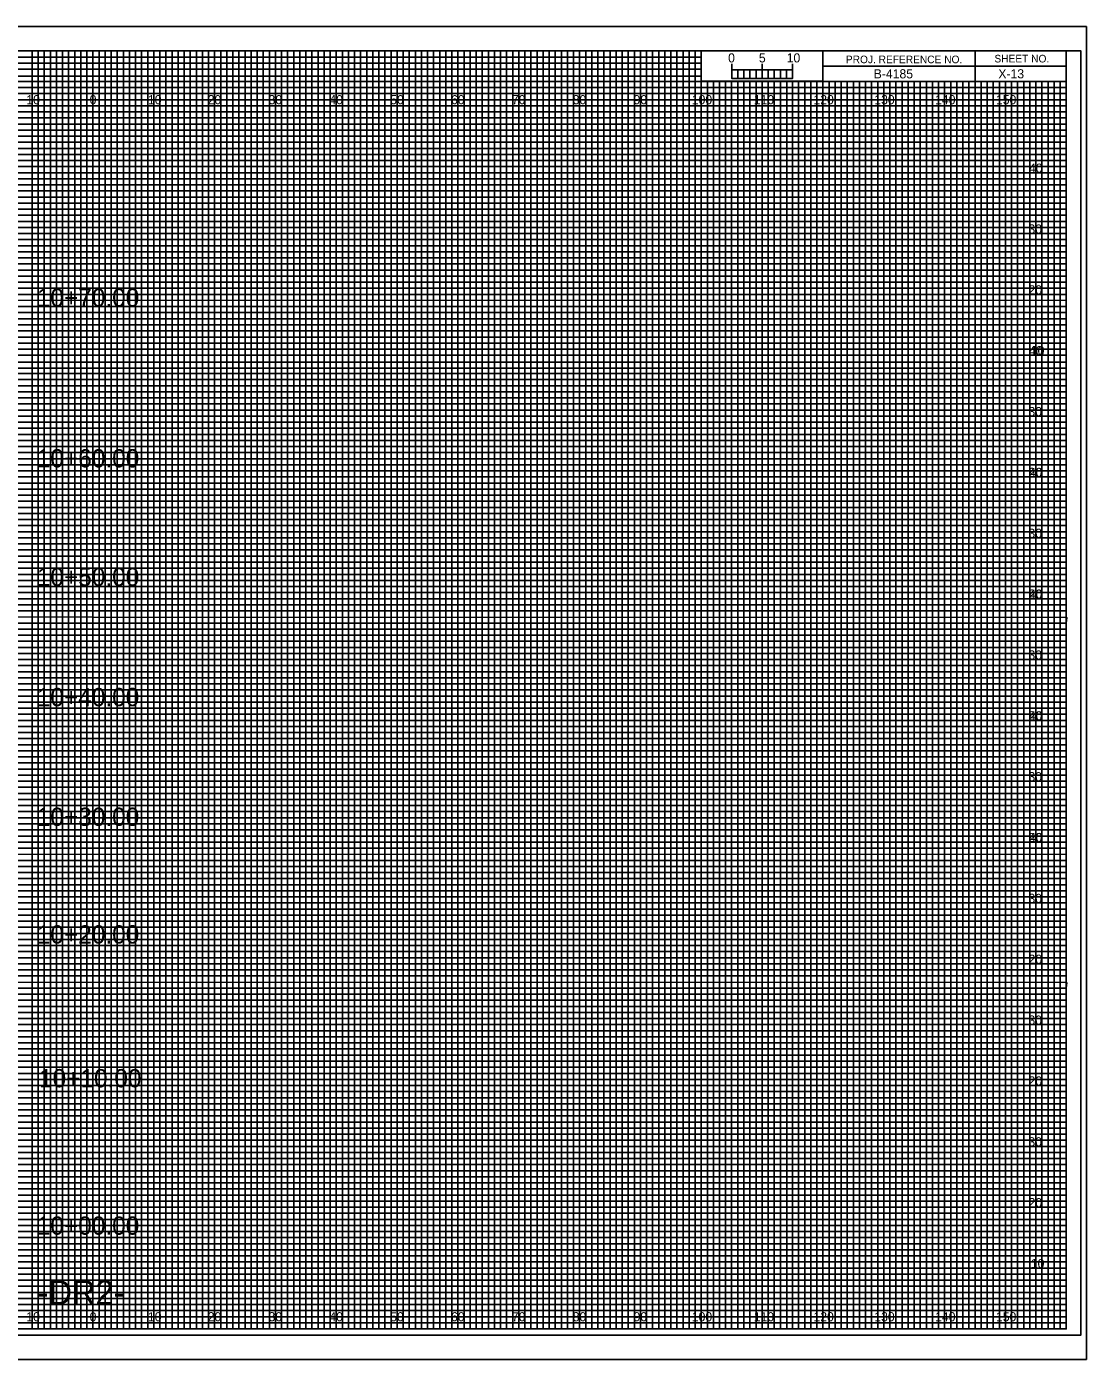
# Model space of a CAD drawing. Extents: x -13 to 323, y -5 to 214.
# Drawn here: x 149.1 to 323.3, y -5 to 214 of the extents above; entities that cross this region are included whole.
import ezdxf

# ---------------------------------------------------------------- set-up
doc = ezdxf.new("R2010")
doc.units = 0
for name, color, linetype in [('Prop XS Alignment Label', 7, 'Continuous'), ('Prop XS Bar Scale Labels', 7, 'Continuous'), ('Prop XS Elevation Labels', 7, 'Continuous'), ('Prop XS Offset Labels', 7, 'Continuous'), ('Prop XS Project Number', 7, 'Continuous'), ('Prop XS Sheet Number', 7, 'Continuous'), ('Prop XS Station Labels', 7, 'Continuous'), ('Sheet Cross Section CELL', 7, 'Continuous'), ('Sheet Cross Section Grid Major CELL', 7, 'Continuous'), ('Sheet Cross Section Grid Middle CELL', 7, 'Continuous'), ('Sheet Cross Section Grid Minor 1 CELL', 7, 'Continuous'), ('Sheet Cross Section Grid Minor 2 CELL', 7, 'Continuous'), ('Sheet Cross Section Scale CELL', 7, 'Continuous'), ('Sheet Cutting Line CELL', 7, 'Continuous'), ('Sheet DOT Grid CELL', 7, 'Continuous'), ('Sheet Plot Border Inside CELL', 7, 'Continuous'), ('Sheet Plot Border Outside CELL', 7, 'Continuous')]:
    doc.layers.add(name, color=color, linetype=linetype)

msp = doc.modelspace()

# ---------------------------------------------------------------- linework, layer by layer
at = {"layer": 'Sheet Cross Section CELL'}
for p, q in [((305, 210), (305, 205)), ((305, 205), (305, 210)), ((280, 207.5), (280, 205)), ((320, 207.49), (280, 207.49)), ((280, 205), (320, 205))]:
    msp.add_line(p, q, dxfattribs=at)
for points in [[(320, 210), (0, 210), (0, 0), (320, 0)], [(280, 210), (260, 210), (260, 205.03), (280, 205.03)], [(320, 210), (280, 210), (280, 205), (320, 205)]]:
    msp.add_lwpolyline(points, close=True, dxfattribs=at)
at = {"layer": 'Sheet Cross Section Grid Major CELL'}
for p, q in [((150, 210), (140, 210)), ((150, 0), (150, 210)), ((170, 210), (160, 210)), ((160, 210), (160, 0)), ((170, 0), (170, 210)), ((190, 210), (180, 210)), ((180, 210), (180, 0)), ((190, 0), (190, 210)), ((210, 210), (200, 210)), ((200, 210), (200, 0)), ((210, 0), (210, 210)), ((230, 210), (220, 210)), ((220, 210), (220, 0)), ((230, 0), (230, 210)), ((250, 210), (240, 210)), ((240, 210), (240, 0)), ((250, 0), (250, 210)), ((260, 210), (260, 0)), ((270, 0), (270, 205)), ((290, 205), (280, 205)), ((280, 205), (280, 0)), ((290, 0), (290, 205)), ((310, 205), (300, 205)), ((300, 205), (300, 0)), ((310, 0), (310, 205)), ((160, 0), (150, 0)), ((180, 0), (170, 0)), ((200, 0), (190, 0)), ((220, 0), (210, 0)), ((240, 0), (230, 0)), ((260, 0), (250, 0)), ((280, 0), (270, 0)), ((300, 0), (290, 0)), ((320, 0), (310, 0)), ((320, 0), (320, 0))]:
    msp.add_line(p, q, dxfattribs=at)
for points in [[(0, 200), (320, 200), (320, 190), (0, 190)], [(0, 180), (320, 180), (320, 170), (0, 170)], [(0, 160), (320, 160), (320, 150), (0, 150)], [(0, 140), (320, 140), (320, 130), (0, 130)], [(0, 120), (320, 120), (320, 110), (0, 110)], [(0, 100), (320, 100), (320, 90), (0, 90)], [(0, 80), (320, 80), (320, 70), (0, 70)], [(0, 60), (320, 60), (320, 50), (0, 50)], [(0, 40), (320, 40), (320, 30), (0, 30)], [(0, 20), (320, 20), (320, 10), (0, 10)]]:
    msp.add_lwpolyline(points, dxfattribs=at)
at = {"layer": 'Sheet Cross Section Grid Middle CELL'}
for points in [[(145, 0), (155, 0), (155, 210), (165, 210), (165, 0), (175, 0), (175, 210), (185, 210), (185, 0), (195, 0), (195, 210), (205, 210), (205, 0), (215, 0), (215, 210), (225, 210), (225, 0), (235, 0), (235, 210), (245, 210), (245, 0), (255, 0), (255, 210), (259.93, 210), (260, 210), (260, 205), (264.99, 205), (264.99, 0), (275, 0), (275, 205), (285, 205), (285, 0), (295, 0), (295, 205), (305, 205), (305, 0), (315, 0), (315, 205)], [(0, 205), (275, 205)], [(0, 185), (320, 185), (320, 195), (0, 195)], [(0, 165), (320, 165), (320, 175), (0, 175)], [(0, 145), (320, 145), (320, 155), (0, 155)], [(0, 125), (320, 125), (320, 135), (0, 135)], [(0, 105), (320, 105), (320, 115), (0, 115)], [(0, 85), (320, 85), (320, 95), (0, 95)], [(0, 65), (320, 65), (320, 75), (0, 75)], [(0, 45), (320, 45), (320, 55), (0, 55)], [(0, 25), (320, 25), (320, 35), (0, 35)], [(0, 5), (320, 5), (320, 15), (0, 15)]]:
    msp.add_lwpolyline(points, dxfattribs=at)
at = {"layer": 'Sheet Cross Section Grid Minor 1 CELL'}
for p, q in [((0, 209), (260, 209)), ((260, 209), (260, 207.98)), ((260, 207.98), (0, 207.98)), ((0, 207), (260, 207)), ((260, 205.89), (0, 205.89)), ((260, 207), (260, 205.89)), ((0, 204), (320, 204))]:
    msp.add_line(p, q, dxfattribs=at)
for points in [[(0, 203), (270, 203), (320, 203), (320, 202), (0, 202)], [(0, 201), (320, 201), (320, 199), (0, 199)], [(0, 198), (320, 198), (320, 197), (0, 196.98)], [(0, 196), (320, 196), (320, 194), (0, 194)], [(0, 193), (320, 193), (320, 192), (0, 192)], [(0, 191), (320, 191), (320, 189), (0, 189)], [(0, 188), (320, 188), (320, 187), (0, 187)], [(0, 186), (320, 186), (320, 184), (0, 184)], [(0, 183), (320, 183), (320, 182), (0, 182)], [(0, 181), (320, 181), (320, 179), (0, 179)], [(0, 178), (320, 178), (320, 177), (0, 177)], [(0, 176), (320, 176), (320, 173.95), (320, 173), (320, 172), (0, 172)], [(0, 174), (320, 174), (320, 173), (0, 173)], [(0, 171), (320, 171), (320, 169), (0, 169.03)], [(0, 169.03), (320, 169), (320, 168), (0, 168)], [(0, 167), (320, 167), (320, 166), (0, 166)], [(0, 164), (320, 164), (320, 163), (0, 163)], [(0, 162), (320, 162), (320, 161), (0, 161)], [(-0.07, 158.89), (320, 158.89), (320, 157.88), (-0.07, 157.88)], [(0, 157), (320, 157), (320, 156), (0, 156)], [(0, 154), (320, 154), (320, 153), (0, 153)], [(0, 152), (320, 152), (320, 151), (0, 151)], [(0, 149), (320, 149), (320, 148), (0, 148)], [(0, 147), (320, 147), (320, 146), (0, 146)], [(0, 144), (320, 144), (320, 143), (0, 143)], [(0, 142), (320, 142), (320, 141), (0, 141)], [(0, 139), (320, 139), (319.99, 137.98), (0, 138)], [(0, 137), (320, 137), (320, 136), (0, 136)], [(0, 134), (320, 134), (320, 133), (0, 133)], [(0, 132), (320, 132), (320, 131), (0, 131)], [(0, 129), (320, 129), (320, 128), (0, 128)], [(0, 127), (320, 127), (320, 126), (0, 126)], [(0, 124), (320, 124), (320, 123), (0, 123)], [(0, 122), (320, 122), (320, 121), (0, 121)], [(0, 119), (320, 119), (320, 118), (0, 118)], [(0, 116.99), (320.07, 116.91), (320, 116), (0, 116)], [(0, 114), (320, 114), (320, 113), (0, 113)], [(0, 112), (320, 112), (320, 111), (0, 111)], [(0, 109), (320, 109), (320, 108), (0, 108)], [(0, 107), (320, 107), (320, 106), (0, 106)], [(0, 104), (320, 104), (320, 103), (0, 103)], [(0, 102), (320, 102), (320, 101), (0, 101)], [(0, 99), (320, 99), (320, 98), (0, 98)], [(0, 97), (320, 97), (320, 96), (0, 96)], [(0, 94), (320, 94), (320, 93), (0, 93)], [(0, 92), (320, 92), (320, 91), (0, 91)], [(0, 89), (320, 89), (320, 88), (0, 88)], [(0, 87), (320, 87), (320, 86), (0, 86)], [(0, 84), (320, 84), (320, 83), (0, 83)], [(0, 82), (320, 82), (320, 81), (0, 81)], [(0, 79), (320, 79), (319.99, 77.98), (0, 78)], [(0, 77), (320, 77), (320, 76), (0, 76)], [(0, 74), (320, 74), (320, 73), (0, 73)], [(0, 72), (320, 72), (320, 71), (0, 71)], [(0, 69), (320, 69), (320, 68), (0, 68)], [(0, 67), (320, 67), (320, 66), (0, 66)], [(0, 64), (320, 64), (320, 63), (0, 63)], [(0, 62), (320, 62), (320, 61), (0, 61)], [(0, 59), (320, 59), (320, 58), (0, 58)], [(0, 56.99), (320.07, 56.91), (320, 56), (0, 56)], [(0, 54), (320, 54), (320, 53), (0, 53)], [(0, 52), (320, 52), (320, 51), (0, 51)], [(0, 49), (320, 49), (320, 48), (0, 48)], [(0, 47), (320, 47), (320, 46), (0, 46)], [(0, 44), (320, 44), (320, 43), (0, 43)], [(0, 42), (320, 42), (320, 41), (0, 41)], [(0, 39), (320, 39), (320, 38), (0, 38)], [(0, 37), (320, 37), (320, 36), (0, 36)], [(0, 34), (320, 34), (320, 33), (0, 33)], [(0, 32), (320, 32), (320, 31), (0, 31)], [(0, 29), (320, 29), (320, 28), (0, 28)], [(0, 27), (320, 27), (320, 26), (0, 26)], [(0, 24), (320, 24), (320, 23), (0, 23)], [(0, 22), (320, 22), (320, 21), (0, 21)], [(0, 19), (320, 19), (320, 18), (0, 18)], [(0, 17), (320, 17), (320, 16), (0, 16)], [(0, 14), (320, 14), (320, 13), (0, 13)], [(0, 12), (320, 12), (320, 11), (0, 11)], [(0, 9), (320, 9), (320, 8), (0, 8)], [(0, 7), (320, 7), (320, 6), (0, 6)], [(0, 4), (320, 4), (320, 3), (0, 3)], [(0, 2), (320, 2), (320, 1), (0, 1)]]:
    msp.add_lwpolyline(points, dxfattribs=at)
at = {"layer": 'Sheet Cross Section Grid Minor 2 CELL'}
for p, q in [((267, 205), (266.01, 205)), ((266.01, 205), (266.01, 0)), ((267, 0), (267, 205)), ((269, 205), (268, 205)), ((268, 205), (268, 0)), ((269, 0), (269, 205)), ((266.01, 0), (265, 0)), ((268, 0), (267, 0))]:
    msp.add_line(p, q, dxfattribs=at)
for points in [[(150, 0), (151, 0), (151, 210), (152, 210), (152, 0)], [(152, 0), (153, 0), (153, 210), (154, 210), (154, 0)], [(155, 0), (156, 0), (156, 210), (157, 210), (157, 0)], [(157, 0), (158, 0), (158, 210), (159, 210), (159, 0)], [(160, 0), (161, 0), (161, 210), (162, 210), (162, 0)], [(162, 0), (163, 0), (163, 210), (164, 210), (164, 0)], [(165, 0), (166, 0), (166, 210), (167, 210), (167, 0)], [(167, 0), (168, 0), (168, 210), (169, 210), (169, 0)], [(170, 0), (171, 0), (171, 210), (172, 210), (172, 0)], [(172, 0), (173, 0), (173, 210), (174, 210), (174, 0)], [(175, 0), (176, 0), (176, 210), (177, 210), (177, 0)], [(177, 0), (178, 0), (178, 210), (179, 210), (179, 0)], [(180, 0), (181, 0), (181, 210), (182, 210), (182, 0)], [(182, 0), (183, 0), (183, 210), (184, 210), (184, 0)], [(185, 0), (186, 0), (186, 210), (187, 210), (187, 0)], [(187, 0), (188, 0), (188, 210), (189, 210), (189, 0)], [(190, 0), (191, 0), (191, 210), (192, 210), (192, 0)], [(192, 0), (193, 0), (193, 210), (194, 210), (194, 0)], [(195, 0), (196, 0), (196, 210), (197, 210), (197, 0)], [(197, 0), (198, 0), (198, 210), (199, 210), (199, 0)], [(200, 0), (201, 0), (201, 210), (202, 210), (202, 0)], [(202, 0), (203, 0), (203, 210), (204, 210), (204, 0)], [(205, 0), (206, 0), (206, 210), (207, 210), (207, 0)], [(207, 0), (208, 0), (208, 210), (209, 210), (209, 0)], [(210, 0), (211, 0), (211, 210), (212, 210), (212, 0)], [(212, 0), (213, 0), (213, 210), (214, 210), (214, 0)], [(215, 0), (216, 0), (216, 210), (217, 210), (217, 0)], [(217, 0), (218, 0), (218, 210), (219, 210), (219, 0)], [(220, 0), (221, 0), (221, 210), (222, 210), (222, 0)], [(222, 0), (223, 0), (223, 210), (224, 210), (224, 0)], [(225, 0), (226, 0), (226, 210), (227, 210), (227, 0)], [(227, 0), (228, 0), (228, 210), (229, 210), (229, 0)], [(230, 0), (231, 0), (231, 210), (232, 210), (232, 0)], [(232, 0), (233, 0), (233, 210), (234, 210), (234, 0)], [(235, 0), (236, 0), (236, 210), (237, 210), (237, 0)], [(237, 0), (238, 0), (238, 210), (239, 210), (239, 0)], [(240, 0), (241, 0), (241, 210), (242, 210), (242, 0)], [(242, 0), (243, 0), (243, 210), (244, 210), (244, 0)], [(245, 0), (246, 0), (246, 210), (247, 210), (247, 0)], [(247, 0), (248, 0), (248, 210), (249, 210), (249, 0)], [(250, 0), (251, 0), (251, 210), (252, 210), (252, 0)], [(252, 0), (253, 0), (253, 210), (254, 210), (254, 0)], [(255, 0), (256, 0), (256, 210), (257, 210), (257, 0)], [(257, 0), (258, 0), (258, 210), (259, 210), (259, 0)], [(260, 0), (261, 0), (261, 205), (262.02, 205), (262.02, 0)], [(262, 0), (263, 0), (263, 205), (263.99, 205), (263.99, 0)], [(270, 0), (270.98, 0), (270.98, 205), (272, 205), (272, 0)], [(272, 0), (273, 0), (273, 205), (274.05, 205), (274.05, 0)], [(275, 0), (276, 0), (276, 205), (277, 205), (277, 0)], [(277, 0), (278, 0), (278, 205), (279, 205), (279, 0)], [(280, 0), (281, 0), (281, 205), (282, 205), (282, 0)], [(282, 0), (283, 0), (283, 205), (284, 205), (284, 0)], [(285, 0), (286, 0), (286, 205), (287, 205), (287, 0)], [(287, 0), (288, 0), (288, 205), (289, 205), (289, 0)], [(290, 0), (291, 0), (291, 205), (292, 205), (292, 0)], [(292, 0), (293, 0), (293, 205), (294, 205), (294, 0)], [(295, 0), (296, 0), (296, 205), (297, 205), (297, 0)], [(297, 0), (298, 0), (298, 205), (299, 205), (299, 0)], [(300, 0), (301, 0), (301, 205), (302, 205), (302, 0)], [(302, 0), (303, 0), (303, 205), (304, 205), (304, 0)], [(305, 0), (306, 0), (306, 205), (307, 205), (307, 0)], [(307, 0), (308, 0), (308, 205), (309, 205), (309, 0)], [(310, 0), (311, 0), (311, 205), (312, 205), (312, 0)], [(312, 0), (313, 0), (313, 205), (314, 205), (314, 0)], [(315, 0), (316, 0), (316, 205), (317, 205), (317, 0)], [(317, 0), (318, 0), (318, 205), (319, 205), (319, 0)]]:
    msp.add_lwpolyline(points, dxfattribs=at)
at = {"layer": 'Sheet Cross Section Scale CELL'}
for p, q in [((265, 205.49), (265, 207.9)), ((265, 206.9), (265, 207.9)), ((270, 205.49), (270, 207.9)), ((275, 205.49), (275, 207.9)), ((275, 206.9), (275, 207.9))]:
    msp.add_line(p, q, dxfattribs=at)
for points in [[(275, 206.9), (265, 206.9), (265, 205.49), (275, 205.49)], [(265, 206.9), (266, 206.9), (266, 205.49), (265, 205.49)], [(267, 206.9), (268, 206.9), (268, 205.49), (267, 205.49)], [(269, 206.9), (270, 206.9), (270, 205.49), (269, 205.49)], [(271, 206.9), (272, 206.9), (272, 205.49), (271, 205.49)], [(273, 206.9), (274, 206.9), (274, 205.49), (273, 205.49)]]:
    msp.add_lwpolyline(points, close=True, dxfattribs=at)
at = {"layer": 'Sheet Cutting Line CELL'}
for p, q in [((323.3, 214), (-13.4, 214)), ((-13.4, -5), (323.3, -5))]:
    msp.add_line(p, q, dxfattribs=at)
at = {"layer": 'Sheet DOT Grid CELL'}
for p, q in [((150, 0), (150, 210)), ((160, 0), (160, 210)), ((170, 0), (170, 210)), ((180, 0), (180, 210)), ((190, 0), (190, 210)), ((200, 0), (200, 210)), ((210, 0), (210, 210)), ((220, 0), (220, 210)), ((230, 0), (230, 210)), ((240, 0), (240, 210)), ((250, 0), (250, 210)), ((260, 0), (260, 204.69)), ((270, 0), (270, 204.69)), ((280, 0), (280, 204.69)), ((290, 0), (290, 204.69)), ((300, 0), (300, 204.69)), ((310, 0), (310, 204.69)), ((0, 200), (320, 200)), ((0, 190), (320, 190)), ((0, 180), (320, 180)), ((0, 170), (320, 170)), ((0, 160), (320, 160)), ((0, 150), (320, 150)), ((0, 140), (320, 140)), ((0, 130), (320, 130)), ((0, 120), (320, 120)), ((0, 110), (320, 110)), ((0, 100), (320, 100)), ((0, 90), (320, 90)), ((0, 80), (320, 80)), ((0, 70), (320, 70)), ((0, 60), (320, 60)), ((0, 50), (320, 50)), ((0, 40), (320, 40)), ((0, 30), (320, 30)), ((0, 20), (320, 20)), ((0, 10), (320, 10))]:
    msp.add_line(p, q, dxfattribs=at)
at = {"layer": 'Sheet Plot Border Inside CELL'}
msp.add_lwpolyline([(-10.8, -1), (322.4, -1), (322.4, 210), (-10.8, 210)], close=True, dxfattribs=at)
at = {"layer": 'Sheet Plot Border Outside CELL'}
msp.add_lwpolyline([(-13.4, -5), (323.3, -5), (323.3, 214), (-13.4, 214)], close=True, dxfattribs=at)

# ---------------------------------------------------------------- texts
at = {"layer": 'Prop XS Alignment Label'}
msp.add_text('-DR2-', height=4, dxfattribs=at).set_placement((150.91, 4))
at = {"layer": 'Prop XS Bar Scale Labels'}
for s, p in [('5', (269.47, 208.12)), ('10', (274.04, 208.12))]:
    msp.add_text(s, height=1.5, dxfattribs=at).set_placement(p)
at = {"layer": 'Prop XS Elevation Labels'}
for s, p in [('40', (313.87, 190)), ('30', (313.78, 180)), ('20', (313.8, 170)), ('40', (313.87, 160)), ('10', (314.17, 160)), ('30', (313.78, 150)), ('20', (313.8, 140)), ('40', (313.87, 140)), ('30', (313.78, 130)), ('20', (313.8, 120)), ('40', (313.87, 120)), ('30', (313.78, 110)), ('20', (313.8, 100)), ('40', (313.87, 100)), ('30', (313.78, 90)), ('20', (313.8, 80)), ('40', (313.87, 80)), ('30', (313.78, 70)), ('20', (313.8, 60)), ('30', (313.78, 50)), ('20', (313.8, 40)), ('30', (313.78, 30)), ('20', (313.8, 20)), ('10', (314.17, 10))]:
    msp.add_text(s, height=1.5, dxfattribs=at).set_placement(p)
at = {"layer": 'Prop XS Offset Labels'}
for s, p in [('10', (149.04, 201.25)), ('0', (159.45, 201.25)), ('0', (159.45, 201.25)), ('10', (169.04, 201.25)), ('20', (178.86, 201.25)), ('30', (188.86, 201.25)), ('40', (198.86, 201.25)), ('50', (208.86, 201.25)), ('60', (218.86, 201.25)), ('70', (228.86, 201.25)), ('80', (238.86, 201.25)), ('90', (248.86, 201.25)), ('100', (258.44, 201.25)), ('110', (268.62, 201.25)), ('120', (278.44, 201.25)), ('130', (288.44, 201.25)), ('140', (298.44, 201.25)), ('150', (308.44, 201.25)), ('10', (149.04, 1.25)), ('0', (159.45, 1.25)), ('0', (159.45, 1.25)), ('10', (169.04, 1.25)), ('20', (178.86, 1.25)), ('30', (188.86, 1.25)), ('40', (198.86, 1.25)), ('50', (208.86, 1.25)), ('60', (218.86, 1.25)), ('70', (228.86, 1.25)), ('80', (238.86, 1.25)), ('90', (248.86, 1.25)), ('100', (258.44, 1.25)), ('110', (268.62, 1.25)), ('120', (278.44, 1.25)), ('130', (288.44, 1.25)), ('140', (298.44, 1.25)), ('150', (308.44, 1.25))]:
    msp.add_text(s, height=1.5, dxfattribs=at).set_placement(p)
at = {"layer": 'Prop XS Project Number'}
msp.add_text('B-4185', height=1.5, dxfattribs=at).set_placement((288.34, 205.5))
at = {"layer": 'Prop XS Sheet Number'}
msp.add_text('X-13', height=1.5, dxfattribs=at).set_placement((308.83, 205.5))
at = {"layer": 'Prop XS Station Labels'}
for s, p in [('10+70.00', (150.77, 167.97)), ('10+60.00', (150.77, 141.57)), ('10+50.00', (150.77, 122.08)), ('10+40.00', (150.77, 102.33)), ('10+30.00', (150.77, 82.66)), ('10+20.00', (150.77, 63.33)), ('10+10.00', (151.13, 39.7)), ('10+00.00', (150.77, 15.48))]:
    msp.add_text(s, height=3, dxfattribs=at).set_placement(p)
at = {"layer": 'Sheet Cross Section CELL'}
for s, p in [('PROJ. REFERENCE NO.', (283.77, 207.99)), ('SHEET NO.', (308.19, 208.12))]:
    msp.add_text(s, height=1.25, dxfattribs=at).set_placement(p)
at = {"layer": 'Sheet Cross Section Scale CELL'}
msp.add_text('0', height=1.5, dxfattribs=at).set_placement((264.41, 208.12))

doc.saveas('drawing.dxf')
